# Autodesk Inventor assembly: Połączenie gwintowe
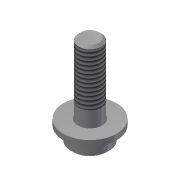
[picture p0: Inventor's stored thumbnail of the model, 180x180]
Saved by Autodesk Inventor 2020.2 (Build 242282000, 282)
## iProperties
Manager: www.cadconsulting.pl
Company: Fabian Stasiak CAD Consulting
ClientObjectVersion: 1
Created: 2011-01
Part Number: Połączenie gwintowe
Document SubType Name: Assembly
Designer: F.Stasiak
Author: F.Stasiak
Subject: Zbiór ćwiczeń. Autodesk Inventor 2020. Kurs podstawowy
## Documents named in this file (3)
- C:\2020_Kurs_podstawowy\R6 Zespoły\Kolizja\100-000\Design Accelerator\Połączenie gwintowe7.iam
- C:\2020_Kurs_podstawowy\Zasoby\Content Center Files\pl-PL\DIN 6796\DIN 6796 - 6.ipt
- C:\2020_Kurs_podstawowy\Zasoby\Content Center Files\pl-PL\DIN 6912\DIN 6912 - M6 x 20.ipt
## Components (2 placed, 2 different names)
1. DIN 6796 6:1
2. DIN 6912 M6 x 20:1
